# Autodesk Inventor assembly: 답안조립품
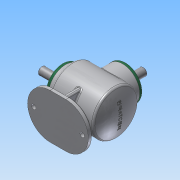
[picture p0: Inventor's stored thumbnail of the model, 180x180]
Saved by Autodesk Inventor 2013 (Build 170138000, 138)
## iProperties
Created: 2016-04
Part Number: 답안조립품
Document SubType Name: Assembly
Designer: Administrator
Author: Administrator
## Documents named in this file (14)
- C:\Users\Administrator\Desktop\460408V1010\답안조립품.iam
- C:\Users\Administrator\Desktop\460408V1010\M4.ipt
- C:\Users\Administrator\Desktop\460408V1010\메인 베벨기어.ipt
- C:\Users\Administrator\Desktop\460408V1010\메인 축.ipt
- 메인 축.ipt
- C:\Users\Administrator\Desktop\460408V1010\베어링 6203.ipt
- C:\Users\Administrator\Desktop\460408V1010\본체.ipt
- C:\Users\Administrator\Desktop\460408V1010\서브 베벨기어.ipt
- C:\Users\Administrator\Desktop\460408V1010\서브 축.ipt
- 서브 축.ipt
- C:\Users\Administrator\Desktop\460408V1010\오일실 17 32 8.ipt
- C:\Users\Administrator\Desktop\460408V1010\커버.ipt
- C:\Users\Administrator\Desktop\460408V1010\키 4x4.ipt
- C:\Users\Administrator\Desktop\460408V1010\키 5x5.ipt
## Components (8 placed, 1 different names)
1. M4:1
2. M4:3
3. M4:4
4. M4:5
5. M4:2
6. M4:6
7. M4:7
8. M4:8
